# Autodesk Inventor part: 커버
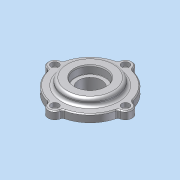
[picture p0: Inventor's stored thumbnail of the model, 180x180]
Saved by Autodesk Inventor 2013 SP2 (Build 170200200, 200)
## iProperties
Company: 한국ATC센터
Created: 2015-03
Part Number: 커버
Document SubType Name: Modeling
Designer: KYOUNG IL JANG
Density: 1 g/cm^3
Material: 일반
Author: KYOUNG IL JANG
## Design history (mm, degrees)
sketch "스케치1"
  geometry: C1 r 1.621 at (0, 6.75) reference; C2 r 1.621 at (-37, -30.25) reference; C3 r 1.621 at (0, -67.25) reference; C4 r 1.621 at (37, -30.25) reference; C5 r 10 at (0, -30.25) reference; C6 r 12 at (0, -30.25); C7 r 24.5 at (0, -30.25) reference; A1 r 3 centre (-38.77, -20.408) between (-38.239, -23.361) and (-35.862, -21.146) reference; A2 r 7 centre (-37, -30.25) between (-38.239, -23.361) and (-38.239, -37.139) reference; A3 r 3 centre (-38.77, -40.092) between (-35.862, -39.354) and (-38.239, -37.139) reference; A4 r 37 centre (0, -30.25) between (-35.862, -39.354) and (-9.104, -66.113) reference; A5 r 3 centre (-9.842, -69.02) between (-6.889, -68.489) and (-9.104, -66.113) reference; A6 r 7 centre (0, -67.25) between (-6.889, -68.489) and (6.889, -68.489) reference; A7 r 3 centre (9.842, -69.02) between (9.104, -66.112) and (6.889, -68.489) reference; A8 r 37 centre (0, -30.25) between (9.104, -66.112) and (35.863, -39.354) reference; A9 r 3 centre (38.77, -40.092) between (38.239, -37.139) and (35.863, -39.354) reference; A10 r 7 centre (37, -30.25) between (38.239, -37.139) and (38.239, -23.361) reference; A11 r 3 centre (38.77, -20.408) between (35.863, -21.146) and (38.239, -23.361) reference; A12 r 37 centre (0, -30.25) between (35.863, -21.146) and (9.104, 5.612) reference; A13 r 3 centre (9.842, 8.52) between (6.889, 7.989) and (9.104, 5.612) reference; A14 r 7 centre (0, 6.75) between (6.889, 7.989) and (-6.889, 7.989) reference; A15 r 3 centre (-9.842, 8.52) between (-9.104, 5.612) and (-6.889, 7.989) reference; A16 r 37 centre (0, -30.25) between (-9.104, 5.612) and (-35.862, -21.146) reference; 1 further point
  constraints: 1 centre point, 1 coincident
  dimensions: "d2" = 2 radial gap between concentric circles of C6 C5
extrude "돌출1" new body sketch "스케치1" distance "d0" = 8; taper "d1" = 0 deg
sketch "스케치2"
  geometry: C1 r 23.5 at (0, -30.25) reference; C2 r 12 at (0, -30.25) reference; 1 further point
extrude "돌출2" join sketch "스케치2" distance "d4" = 5; taper "d5" = 0 deg
sketch "스케치3"
  geometry: C1 r 23.5 at (0, 0) reference; C2 r 20.5 at (0, 0); 1 further point
  constraints: 1 centre point
  dimensions: "d6" = 3 radial gap between concentric circles of C2 C1
node "작업 평면1"
extrude "돌출3" join sketch "스케치3" stored distance "d7" = 5; taper "d8" = 0 deg
fillet "모깎기1" dims "d9" = 3
sketch "스케치4"
  geometry: C1 r 12 at (0, -30.25) reference; C2 r 27 at (0, -30.25); 1 further point
  constraints: 1 centre point
  dimensions: "d10" = 15 radial gap between concentric circles of C1 C2
extrude "돌출4" join sketch "스케치4" distance "d11" = 7; taper "d12" = 0 deg
fillet "모깎기2" dims "d13" = 3
chamfer "모따기1" distance "d14" = 1; stored, may be unused: second distance "d15" = 2, angle "d16" = 45 deg
node "작업점1"
  node "작업축1"
chamfer "모따기2" distance "d24" = 1; stored, may be unused: second distance "d25" = 2, angle "d26" = 45 deg
hole "구멍6" diameter "d43" = 4.5; stored, may be unused: countersink angle "d47" = 90 deg, drill point angle "d49" = 118 deg; dims "d41" = 10, "d42" = 10, "d44" = 6, "d45" = 8, "d46" = 4.4, "d48" = 8
sketch "스케치8"
  geometry: C1 r 12 at (0, 0) reference; C2 r 16 at (0, 0); 1 further point
  constraints: 1 centre point, 1 coincident
  dimensions: "d53" = 32 diameter of C2
extrude "돌출5" cut sketch "스케치8" distance "d54" = 8.3; taper "d55" = 0 deg
fillet "모깎기3" dims "d56" = 0.3
chamfer "모따기3" distance "d57" = 1.2; stored, may be unused: second distance "d58" = 2, angle "d59" = 30 deg
node "솔리드1"
pattern_circular "원형 패턴1" dims angle "d51" = 360 deg
node "참조1"
node "참조2"
